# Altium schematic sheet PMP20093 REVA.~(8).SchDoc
size 431 x 279 mm; Date: Not shown in title block; ApprovedBy: Not shown in title block; CheckedBy: Not shown in title block; Author: Not shown in title block; CompanyName: Not shown in title block; Engineer: Not shown in title block; Organization: Not shown in title block; Address1: Not shown in title block; Address2: Not shown in title block; Address3: Not shown in title block; Address4: Not shown in title block; DocumentNumber: 1; Revision: Use project parameter SCH_Rev; SheetNumber: 2; SheetTotal: 3; PageSetup: Record=PageOptions¦CenterHorizontal=True¦CenterVertical=True¦PrintScale=1.00¦XCorrection=1.00¦YCorrection=1.00¦PrintKind=0¦BorderSize=5000000¦LeftOffset=0¦BottomOffset=0¦Orientation=2¦PaperLength=1000¦PaperWidth=1000¦Scale=100¦PaperSource=15¦PrintQuality=600¦MediaType=1¦DitherType=10¦PaperKind=Letter¦PrintScaleMode=1
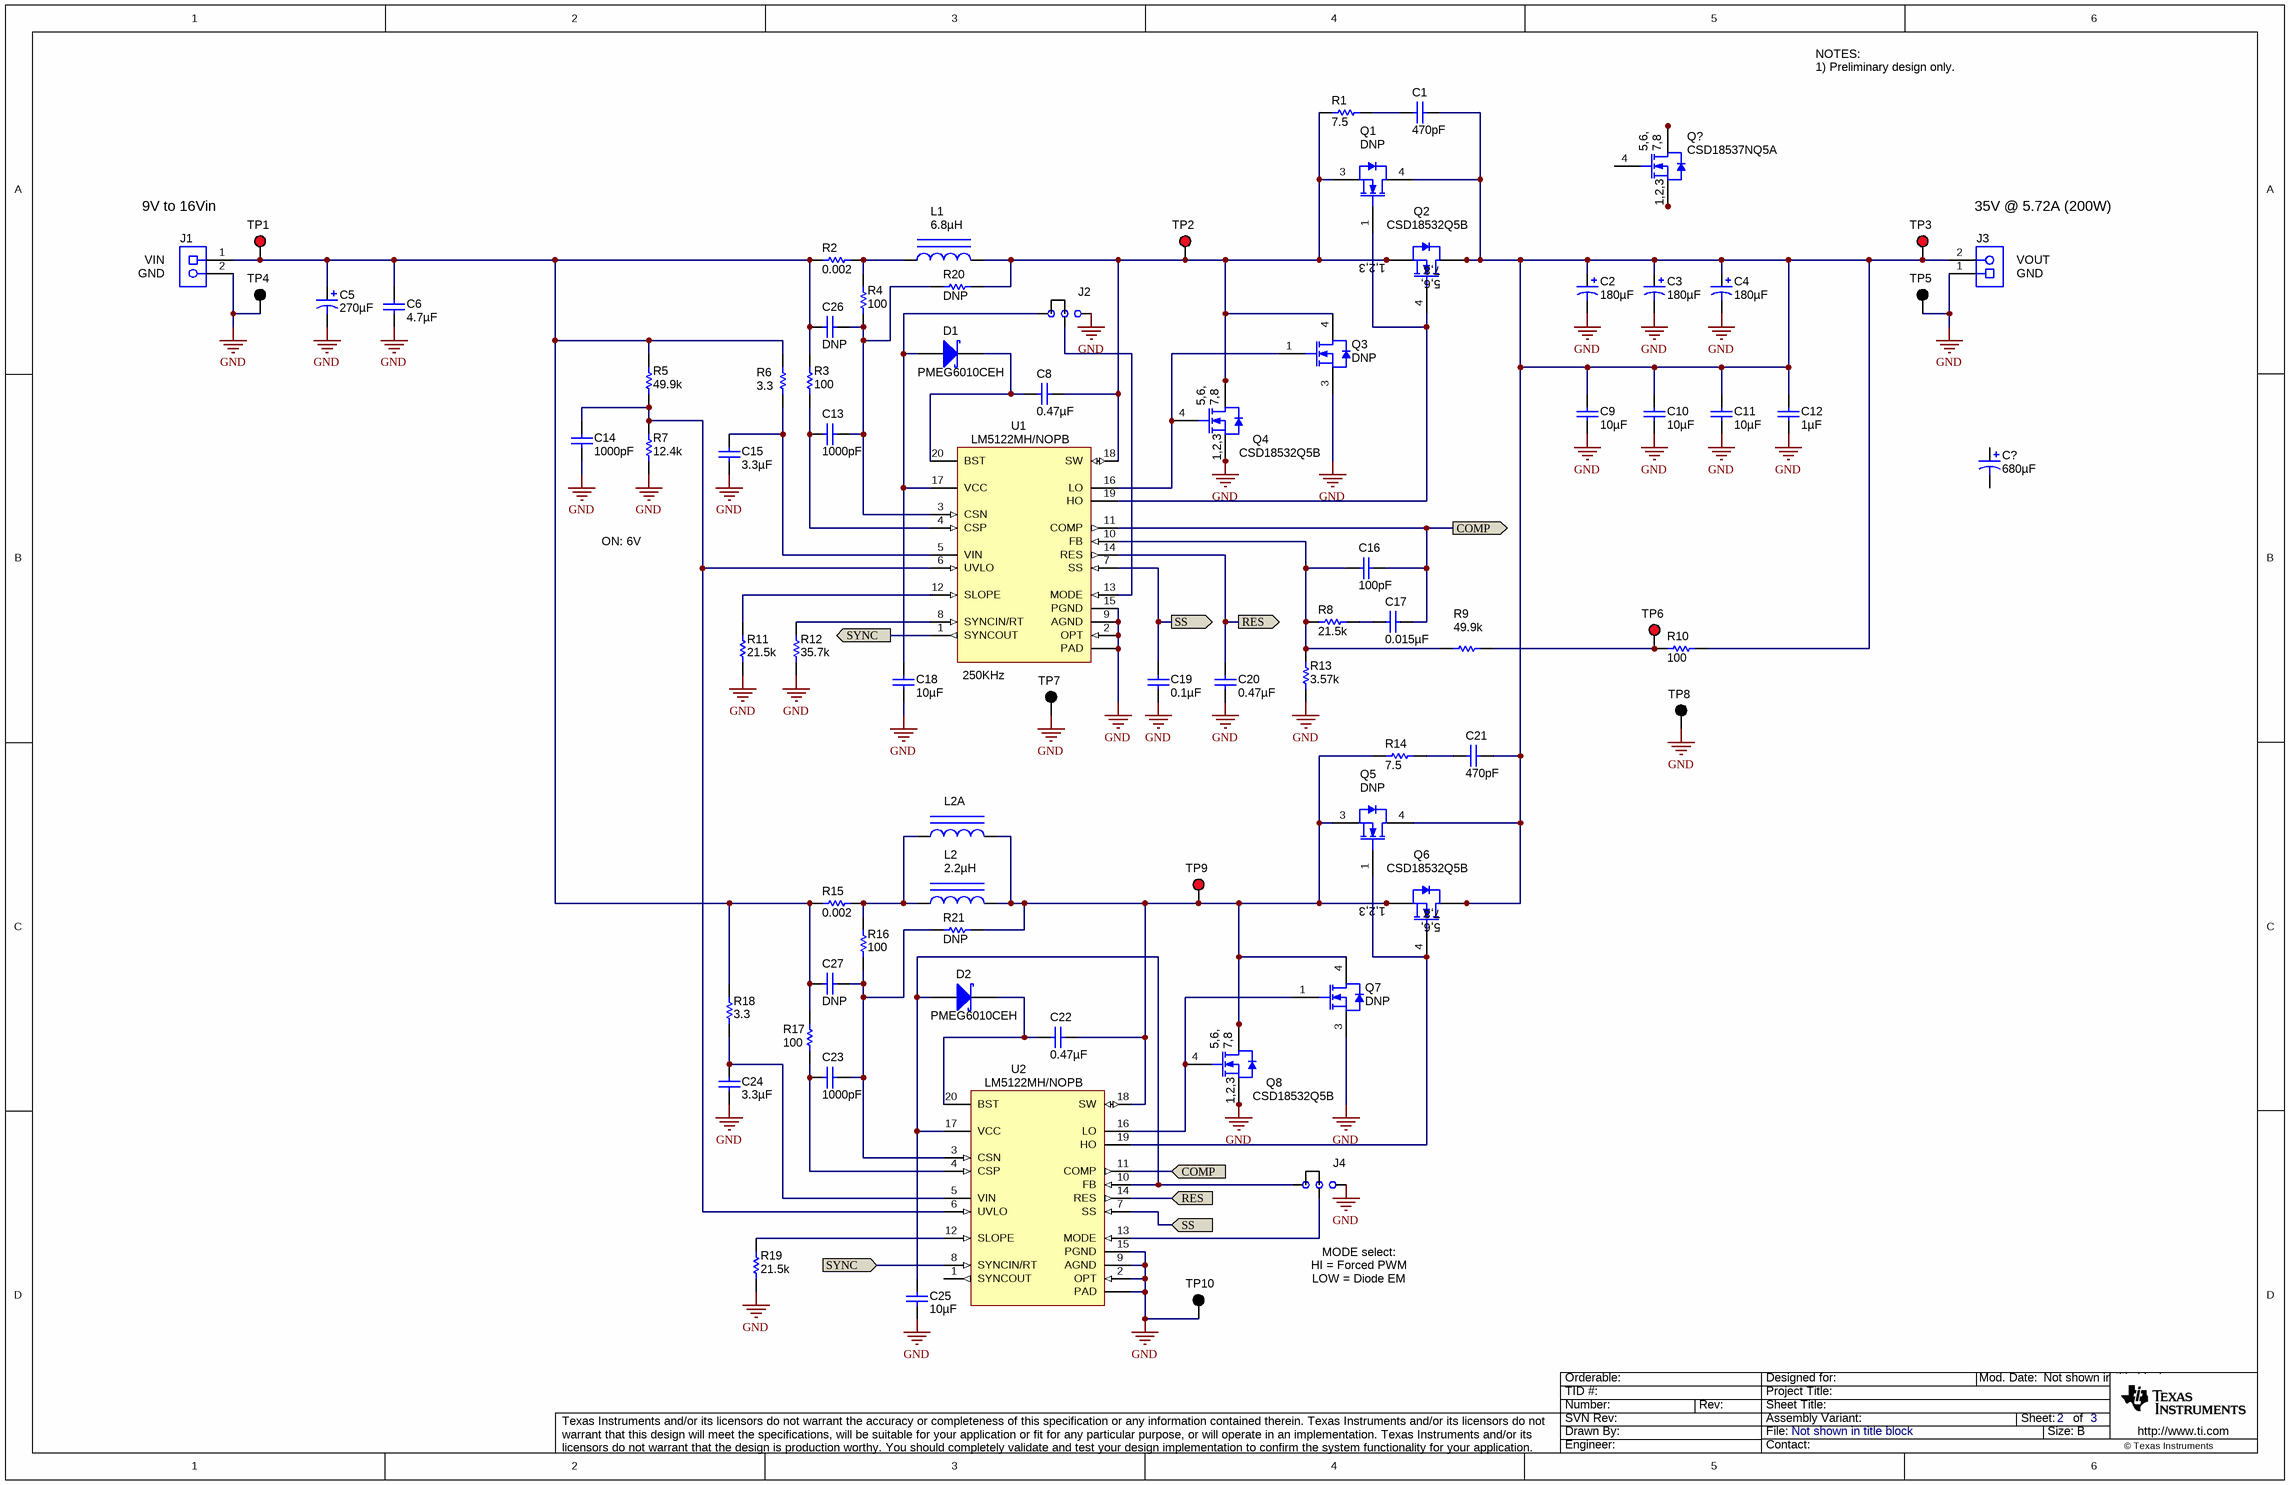
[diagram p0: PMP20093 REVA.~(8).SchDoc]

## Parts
C1  ValueDisplayed: 470pF  [0603]  (hidden comment: C1608C0G1H471J)
C2  ValueDisplayed: 180µF  [SM_RADIAL_8MM]  (hidden comment: 25SVPF180M)
C3  ValueDisplayed: 180µF  [SM_RADIAL_8MM]  (hidden comment: 25SVPF180M)
C4  ValueDisplayed: 180µF  [SM_RADIAL_8MM]  (hidden comment: 25SVPF180M)
C5  ValueDisplayed: 270µF  [SM_RADIAL_10BMM]  (hidden comment: EEHZA1V271P)
C6  ValueDisplayed: 4.7µF  [1210]  (hidden comment: GRM32ER71H475KA88L)
C8  ValueDisplayed: 0.47µF  [0603]  (hidden comment: GRM188R71E474KA12D)
C9  ValueDisplayed: 10µF  [1210]  (hidden comment: C3225X7R1E106M)
C10  ValueDisplayed: 10µF  [1210]  (hidden comment: C3225X7R1E106M)
C11  ValueDisplayed: 10µF  [1210]  (hidden comment: C3225X7R1E106M)
C12  ValueDisplayed: 1µF  [0805_HV]  (hidden comment: C2012X7R1E105K)
C13  ValueDisplayed: 1000pF  [0603]  (hidden comment: GRM188R71H102KA01D)
C14  ValueDisplayed: 1000pF  [0603]  (hidden comment: GRM188R71H102KA01D)
C15  ValueDisplayed: 3.3µF  [1206]  (hidden comment: C3216X7R1H335K160AC)
C16  ValueDisplayed: 100pF  [0603]  (hidden comment: C1608C0G1H101J)
C17  ValueDisplayed: 0.015µF  [0603]  (hidden comment: C1608X7R1H153K)
C18  ValueDisplayed: 10µF  [1206]  (hidden comment: C3216X7R1E106K)
C19  ValueDisplayed: 0.1µF  [0603]  (hidden comment: C1608X7R1H104K)
C20  ValueDisplayed: 0.47µF  [0603]  (hidden comment: GRM188R71E474KA12D)
C21  ValueDisplayed: 470pF  [0603]  (hidden comment: C1608C0G1H471J)
C22  ValueDisplayed: 0.47µF  [0603]  (hidden comment: GRM188R71E474KA12D)
C23  ValueDisplayed: 1000pF  [0603]  (hidden comment: GRM188R71H102KA01D)
C24  ValueDisplayed: 3.3µF  [1206]  (hidden comment: C3216X7R1H335K160AC)
C25  ValueDisplayed: 10µF  [1206]  (hidden comment: C3216X7R1E106K)
C26  ValueDisplayed: DNP  [0603]
C27  ValueDisplayed: DNP  [0603]
C?  ValueDisplayed: 680µF  [ZL_1250x2500]  (hidden comment: 50ZL680MEFC12.5X25)
D1  PMEG6010CEH  [SOD-123F]
D2  PMEG6010CEH  [SOD-123F]
J1  ED120/2DS  [CONN_ED120-2DS]  (value not drawn)
J2  JUMPER_3X100MIL  [HDR100_1X3]  (value not drawn)
J3  ED120/2DS  [CONN_ED120-2DS]  (value not drawn)
J4  JUMPER_3X100MIL  [HDR100_1X3]  (value not drawn)
L1  ValueDisplayed: 6.8µH  [IHLP8787MZ]  (hidden comment: IHLP8787MZER6R8M5A)
L2  ValueDisplayed: 2.2µH  [XAL1010]  (hidden comment: XAL1010-222MEB)
L2A  SER2009-202MLB  [SER2009]  (value not drawn)
Q1  value DNP  [DPAK]
Q2  CSD18532Q5B  [TRANS_NexFET_Q5B]
Q3  value DNP  [DPAK]
Q4  CSD18532Q5B  [TRANS_NexFET_Q5B]
Q5  value DNP  [DPAK]
Q6  CSD18532Q5B  [TRANS_NexFET_Q5B]
Q7  value DNP  [DPAK]
Q8  CSD18532Q5B  [TRANS_NexFET_Q5B]
Q?  CSD18537NQ5A  [TRANS_NexFET_Q5A]
R1  value 7.5  [2010M]  (hidden comment: CRM2010-JW-7R5ELF)
R2  value 0.002  [2512]  (hidden comment: CSNL2512FT2L00)
R3  value 100  [0603_HV]  (hidden comment: ERJ-3GEY0R00V)
R4  value 100  [0603_HV]  (hidden comment: ERJ-3GEY0R00V)
R5  value 49.9k  [0603]  (hidden comment: CRCW060349K9FKEA)
R6  value 3.3  [0603_HV]  (hidden comment: CRCW06033R30JNEA)
R7  value 12.4k  [0603]  (hidden comment: CRCW060312K4FKEA)
R8  value 21.5k  [0603]  (hidden comment: CRCW060321K5FKEA)
R9  value 49.9k  [0603]  (hidden comment: CRCW060349K9FKEA)
R10  value 100  [0603]  (hidden comment: CRCW0603100RFKEA)
R11  value 21.5k  [0603]  (hidden comment: CRCW060321K5FKEA)
R12  ValueDisplayed: 35.7k  [0603]  (hidden comment: CRCW060335K7FKEA)
R13  value 3.57k  [0603]  (hidden comment: CRCW06033K57FKEA)
R14  value 7.5  [2010M]  (hidden comment: CRM2010-JW-7R5ELF)
R15  value 0.002  [2512]  (hidden comment: CSNL2512FT2L00)
R16  value 100  [0603_HV]  (hidden comment: ERJ-3GEY0R00V)
R17  value 100  [0603_HV]  (hidden comment: ERJ-3GEY0R00V)
R18  value 3.3  [0603_HV]  (hidden comment: CRCW06033R30JNEA)
R19  value 21.5k  [0603]  (hidden comment: CRCW060321K5FKEA)
R20  value DNP  [0603]
R21  value DNP  [0603]
TP1  5010  [Keystone5010]  (value not drawn)
TP2  5010  [Keystone5010]  (value not drawn)
TP3  5010  [Keystone5010]  (value not drawn)
TP4  5011  [Keystone5011]  (value not drawn)
TP5  5011  [Keystone5011]  (value not drawn)
TP6  5010  [Keystone5010]  (value not drawn)
TP7  5011  [Keystone5011]  (value not drawn)
TP8  5011  [Keystone5011]  (value not drawn)
TP9  5010  [Keystone5010]  (value not drawn)
TP10  5011  [Keystone5011]  (value not drawn)
U1  LM5122MH/NOPB  [PWP0020A_N]
U2  LM5122MH/NOPB  [PWP0020A_N]

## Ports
COMP, RES, SS, SYNC

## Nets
GND: C2.2(-) C3.2(-) C4.2(-) C5.2(-) C6.2 C9.2 C10.2 C11.2 C12.2 C14.2 C15.2 C18.2 C19.2 C20.1 C24.2 C25.2 J1.2 J2.1 J3.1 J4.1 Q3.3(S) Q4.1(S) Q4.2(S) Q4.3(S) Q7.3(S) Q8.1(S) Q8.2(S) Q8.3(S) R7.1 R11.1 R12.1 R13.1 R19.1 TP4.1 TP5.1 TP7.1 TP8.1 TP10.1 U1.2(OPT) U1.9(AGND) U1.15(PGND) U1.21(PAD) U2.2(OPT) U2.9(AGND) U2.15(PGND) U2.21(PAD)
COMP: C16.2 C17.2 U1.11(COMP) U2.11(COMP) ; port COMP
RES: C20.2 U1.14(RES) U2.14(RES) ; port RES
SS: C19.1 U1.7(SS) U2.7(SS) ; port SS
SYNC: U1.1(SYNCOUT) U2.8(SYNCIN/RT) ; port SYNC
NetC1_1: C1.1 C2.1(+) C3.1(+) C4.1(+) C9.1 C10.1 C11.1 C12.1 C21.1 J3.2 Q1.4(D) Q2.5(D) Q2.6(D) Q2.7(D) Q2.8(D) Q5.4(D) Q6.5(D) Q6.6(D) Q6.7(D) Q6.8(D) R10.2 TP3.1
NetC1_2: C1.2 R1.2
NetC5_1: C5.1(+) C6.1 C26.2 C27.2 J1.1 R2.1 R3.2 R5.2 R6.1 R15.1 R17.2 R18.1 TP1.1
NetC8_1: C8.1 D1.1(K) U1.20(BST)
NetC8_2: C8.2 L1.2 Q1.3(S) Q2.1(S) Q2.2(S) Q2.3(S) Q3.4(D) Q4.5(D) Q4.6(D) Q4.7(D) Q4.8(D) R1.1 R20.2 TP2.1 U1.18(SW)
NetC13_1: C13.1 C26.1 R4.1 R20.1 U1.3(CSN)
NetC13_2: C13.2 R3.1 U1.4(CSP)
NetC14_1: C14.1 R5.1 R7.2 U1.6(UVLO) U2.6(UVLO)
NetC15_1: C15.1 R6.2 U1.5(VIN)
NetC16_1: C16.1 R8.1 R9.1 R13.2 U1.10(FB)
NetC17_1: C17.1 R8.2
NetC18_1: C18.1 D1.2(A) J2.3 U1.17(VCC)
NetC21_2: C21.2 R14.2
NetC22_1: C22.1 D2.1(K) U2.20(BST)
NetC22_2: C22.2 L2.2 L2A.1 Q5.3(S) Q6.1(S) Q6.2(S) Q6.3(S) Q7.4(D) Q8.5(D) Q8.6(D) Q8.7(D) Q8.8(D) R14.1 R21.2 TP9.1 U2.18(SW)
NetC23_1: C23.1 C27.1 R16.1 R21.1 U2.3(CSN)
NetC23_2: C23.2 R17.1 U2.4(CSP)
NetC24_1: C24.1 R18.2 U2.5(VIN)
NetC25_1: C25.1 D2.2(A) J4.3 U2.10(FB) U2.17(VCC)
NetJ2_2: J2.2 U1.13(MODE)
NetJ4_2: J4.2 U2.13(MODE)
NetL1_1: L1.1 R2.2 R4.2
NetL2_1: L2.1 L2A.2 R15.2 R16.2
NetQ1_1: Q1.1(G) Q2.4(G) U1.19(HO)
NetQ3_1: Q3.1(G) Q4.4(G) U1.16(LO)
NetQ5_1: Q5.1(G) Q6.4(G) U2.19(HO)
NetQ7_1: Q7.1(G) Q8.4(G) U2.16(LO)
NetQ?_1: Q?.1(S) Q?.2(S) Q?.3(S)
NetQ?_5: Q?.5(D) Q?.6(D) Q?.7(D) Q?.8(D) Q?.9(D)
NetR9_2: R9.2 R10.1 TP6.1
NetR11_2: R11.2 U1.12(SLOPE)
NetR12_2: R12.2 U1.8(SYNCIN/RT)
NetR19_2: R19.2 U2.12(SLOPE)

Not connected (* = marked no-connect by the designer): C? 1(+) 2(-); Q? 4(G); U2 1(SYNCOUT)

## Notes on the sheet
- NOTES:
  1) Preliminary design only.
- 9V to 16Vin
- 35V @ 5.72A (200W)
- (near J1) VIN
- (near J1) GND
- (near J3) VOUT
- (near J3) GND
- ON: 6V
- (near U1) 250KHz
- MODE select:
- HI = Forced PWM
- LOW = Diode EM

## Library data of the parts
C1 C21 = C1608C0G1H471J: CAP, CERM, 470pF, 50V, +/-5%, C0G/NP0, 0603; Manufacturer: TDK; Polarized: N; CompType: Capacitor; U/M: EA; Cap_F: 0.00000000047; Tolerance_%: 5; ESR_Ohm: 0.0922; Value1: 0.0922 ohm; VDC_V: 50; TaMin_C: -55; TaMax_C: 125
C2-C4 = 4SVP560M: CAP, OS-CON, 180uF, 25V, 4.65Arms, 0.016 ohm, E12; Manufacturer: Sanyo; Polarized: Y; CompType: Capacitor; U/M: EA; Cap_F: 0.00056; Tolerance_%: 20; VDC_V: 25; ESR_Ohm: 0.013; IRMS_A: 4.52; TaMin_C: -55; TaMax_C: 105; Cap_Case: 8.3x8.3x11.9
C5 = EEHZA1V271P: CAP, Polymer Hybrid, 270 µF, 35 V, +/- 20%, 20 ohm, 10x10 SMD; Manufacturer: Panasonic; Polarized: Y; CompType: Capacitor; Value: 270uF; U/M: EA; Cap_F: 0.00027; Tolerance_%: 20; Value1: 20 ohm; VDC_V: 35; Value2: 35V; IRMS_A: 2.5; TaMin_C: -55; TaMax_C: 105; AEC Category: Q200
C6 = GRM32ER71H475KA88L: CAP, CERM, 4.7uF, 50V, +/-10%, X7R, 1210; Manufacturer: MuRata; Polarized: N; CompType: Capacitor; U/M: EA; Cap_F: 0.0000047; Tolerance_%: 10; ESR_Ohm: 0.002; Value1: 0.002 ohm; VDC_V: 50; TaMin_C: -55; TaMax_C: 125
C8 C20 C22 = GRM188R71E474KA12D: CAP, CERM, 0.47uF, 25V, +/-10%, X7R, 0603; Manufacturer: MuRata; Polarized: N; CompType: Capacitor; U/M: EA; Cap_F: 0.00000047; Tolerance_%: 10; Value1: Unknown; VDC_V: 25; TaMin_C: -55; TaMax_C: 125
C9-C11 = C3225X7R1E106M: CAP, CERM, 10uF, 25V, +/-20%, X7R, 1210; Manufacturer: TDK; Polarized: N; CompType: Capacitor; U/M: EA; Cap_F: 0.00001; Tolerance_%: 20; ESR_Ohm: 0.0027; Value1: 0.0027 ohm; VDC_V: 25; IRMS_A: 3; TaMin_C: -55; TaMax_C: 125
C12 = C2012X7R1E105K: CAP, CERM, 1uF, 25V, +/-10%, X7R, 0805; Manufacturer: TDK; Polarized: N; CompType: Capacitor; U/M: EA; Cap_F: 0.000001; Tolerance_%: 10; ESR_Ohm: 0.0075; Value1: 0.0075 ohm; VDC_V: 25; TaMin_C: -55; TaMax_C: 125; Cap_Case: 0805
C13 C14 C23 = GRM188R71H102KA01D: CAP, CERM, 1000pF, 50V, +/-10%, X7R, 0603; Manufacturer: MuRata; Polarized: N; CompType: Capacitor; U/M: EA; Cap_F: 0.000000001; Tolerance_%: 10; Value1: Unknown; VDC_V: 50; TaMin_C: -55; TaMax_C: 125
C15 C24 = C3216X7r1H335K160AC: CAP, CERM, 3.3uF, 50V, +/-10%, X7R, 1206; Manufacturer: TDK; Polarized: N; CompType: Capacitor; U/M: EA; Cap_F: 0.0000033; Tolerance_%: 10; Value1: Unknown; VDC_V: 50; TaMin_C: -55; TaMax_C: 125
C16 = C1608C0G1H101J: CAP, CERM, 100pF, 50V, +/-5%, C0G/NP0, 0603; Manufacturer: TDK; Polarized: N; CompType: Capacitor; U/M: EA; Cap_F: 0.0000000001; Tolerance_%: 5; ESR_Ohm: 0.1679; Value1: 0.1679 ohm; VDC_V: 50; TaMin_C: -55; TaMax_C: 125
C17 = C1608X7R1H103K: CAP, CERM, 0.015uF, 50V, +/-10%, X7R, 0603; Manufacturer: TDK; Polarized: N; CompType: Capacitor; U/M: EA; Cap_F: 0.00000001; Tolerance_%: 10; ESR_Ohm: 0.0539; Value1: 0.0539 ohm; VDC_V: 50; TaMin_C: -55; TaMax_C: 125
C18 C25 = C3216X7R1C475K: CAP, CERM, 10uF, 25V, +/-10%, X7R, 1206; Manufacturer: TDK; Polarized: N; CompType: Capacitor; U/M: EA; Cap_F: 0.0000047; Tolerance_%: 10; ESR_Ohm: 0.0036; Value1: 0.0036 ohm; VDC_V: 25; IRMS_A: 2; TaMin_C: -55; TaMax_C: 125
C19 = C1608X7R1H104K: CAP, CERM, 0.1uF, 50V, +/-10%, X7R, 0603; Manufacturer: TDK; Polarized: N; CompType: Capacitor; U/M: EA; Cap_F: 0.0000001; Tolerance_%: 10; ESR_Ohm: 0.017; Value1: 0.017 ohm; VDC_V: 50; TaMin_C: -55; TaMax_C: 125
C26 C27 = GRM188R71H102KA01D: CAP, DNP; Polarized: N; CompType: Capacitor; U/M: EA; Cap_F: 0.000000001; Value1: Unknown; TempCo: X7R; TaMin_C: -55; TaMax_C: 125
C? = 50ZL560MEFC12.5X25: CAP, AL, 680 µF, 50 V, +/- 20%, 2.86A, 0.021 ohm, TH; Manufacturer: Rubycon; Polarized: Y; CompType: Capacitor; Value: 680uF; U/M: EA; Cap_F: 0.00056; Tolerance_%: 20; VDC_V: 50; Value2: 50V; ESR_ohm: 0.023; IRMS_A: 2.41; TaMin_C: -40; TaMax_C: 105; Cap_Case: 12.5x25mm; AEC Category: Q200; AEC Qualified: N
D1 D2 = PMEG6010CEH,115: Diode, Schottky, 60V, 1A, SOD-123F; Manufacturer: NXP Semiconductor; U/M: EA; Vf_V: 0.57; Value2: 0.57V; Io_A: 1; Vr_V: 60; TJmax_C: 150
J1 J3 = ED120/2DS: TERMINAL BLOCK, 15A, VERT 2POS, TH; Manufacturer: On-Shore Technology; SymbolCreator: a0412235; U/M: EA
J2 J4 = JUMPER_3X100MIL: Header, Male 3-pin, 100mil spacing,; Manufacturer: Sullins; PartNumber: PEC03SAAN; area: 30000; Value: PEC03SAAN
L1 = IHLP8787MZER100M5A: Inductor, Shielded, 6.8 µH, 36A, 0.00284 ohm, AEC-Q200 Grade 0, SMD; Manufacturer: Vishay-Dale; Value: 6.8uH; AEC Category: Q200; AEC Qualified: Y; AEC Grade: 0
L2 = XAL1010-222MEB: Inductor, Shielded, Composite, 2.2uH, 32A, 0.00255 ohm, SMD; Manufacturer: Coilcraft; Ind_H: 2.2E-6; Imax_A: 32; Irms: 32A @ 40C rise; Isat: 34A @ 30% inductance drop; U/M: EA
L2A = SER2009-202MLB: Inductor, Shielded E Core, Ferrite, 2uH, 16A, 0.00063 ohm, SMD; Manufacturer: Coilcraft; Ind_H: 2.0E-6; ValueDisplayed: 2µH; Imax_A: 16; Irms: 54A @ 40C rise; Isat: 16A @ 10% inductance drop; U/M: EA
Q1 Q3 Q5 Q7 = SUD23N06-31L-E3: MOSFET, DPAK, DNP; Manufacturer: Vishay-Siliconix; Alternate Manufacturer: None; U/M: EA; ChType: N; Rdson45_Ohm: 0.045; QgTyp_nC: 11; IdsMax_A: 23
Q2 Q4 Q6 Q8 = CSD18532Q5B: MOSFET, N-CH, 60V, 172A, SON 5x6mm; Manufacturer: Texas Instruments; Alternate Manufacturer: None; U/M: EA; ChType: N; VdsMax_V: 60; Value1: 3.3 ohm; Rdson45_Ohm: 3.3; Value2: 27 nC; QgTyp_nC: 27; Vgs_V: 1.6; IdsMax_A: 172
Q? = CSD18537NQ5A: MOSFET, N-CH, 60 V, 50 A, SON 5x6mm; Manufacturer: Texas Instruments; Alternate Manufacturer: None; U/M: EA; ChType: N; Value: 60V; VdsMax_V: 60; Value1: 0.036 ohm; Rdson45_ohm: 0.036; Value2: 14 nC; QgTyp_nC: 14; Vgs_V: 20; IdsMax_A: 50; AEC Category: Q101
R1 R14 = CRM2010-JW-7R5ELF: RES, 7.5 ohm, 5%, 1W, 2010; Manufacturer: Bourns; CompType: Resistor; Value_Code: 7R50; Tolerance_%: 5; Power_W: 1; VDC_V: 3; TempCo: 100 ppm/C; EIA_Code: E24; U/M: EA
R2 R15 = CSNL2512FT2L00: RES, 0.002 ohm, 1%, 2W, 2512; Manufacturer: Stackpole Electronics Inc; CompType: Resistor; Value_Code: R002; Tolerance_%: 1; Power_W: 2; VDC_V: 200; TempCo: 50 ppm/C; U/M: EA
R3 R4 R16 R17 = ERJ-3GEY0R00V: RES, 0 ohm, 5%, 0.1W, 0603; Manufacturer: Panasonic; CompType: Resistor; Res_ohm: 0; Value_Code: 0000; Tolerance_%: 5; Power_W: 0.1; VDC_V: 50; TempCo: 600 ppm/C; EIA_Code: E24; U/M: EA
R5 R9 = CRCW060349K9FKEA: RES, 49.9k ohm, 1%, 0.1W, 0603; Manufacturer: Vishay-Dale; CompType: Resistor; Res_ohm: 49900; Value_Code: 49k9; Tolerance_%: 1; Power_W: 0.1; VDC_V: 75; TempCo: 100 ppm/C; EIA_Code: E96; U/M: EA
R6 R18 = CRCW06033R30JNEA: RES, 3.3 ohm, 5%, 0.1W, 0603; Manufacturer: Vishay-Dale; CompType: Resistor; Value_Code: 3R30; Tolerance_%: 5; Power_W: 0.1; VDC_V: 75; TempCo: 200 ppm/C; EIA_Code: E24; U/M: EA
R7 = CRCW060312K4FKEA: RES, 12.4k ohm, 1%, 0.1W, 0603; Manufacturer: Vishay-Dale; CompType: Resistor; Res_ohm: 12400; Value_Code: 12k4; Tolerance_%: 1; Power_W: 0.1; VDC_V: 75; TempCo: 100 ppm/C; EIA_Code: E96; U/M: EA
R8 R11 R19 = CRCW060321K5FKEA: RES, 21.5k ohm, 1%, 0.1W, 0603; Manufacturer: Vishay-Dale; CompType: Resistor; Res_ohm: 21500; Value_Code: 21k5; Tolerance_%: 1; Power_W: 0.1; VDC_V: 75; TempCo: 100 ppm/C; EIA_Code: E96; U/M: EA
R10 = CRCW0603100RFKEA: RES, 100 ohm, 1%, 0.1W, 0603; Manufacturer: Vishay-Dale; CompType: Resistor; Value_Code: 100R; Tolerance_%: 1; Power_W: 0.1; VDC_V: 75; TempCo: 100 ppm/C; EIA_Code: E96; U/M: EA
R12 = CRCW060335K7FKEA: RES, 35.7 k, 1%, 0.1 W, 0603; Manufacturer: Vishay-Dale; CompType: Resistor; Value: 35.7k; Res_ohm: 35700; Value_Code: 35k7; Tolerance_%: 1; Power_W: 0.1; Value2: 0.1W; VDC_V: 75; TempCo: 100 ppm/C; EIA_Code: E96; U/M: EA; AEC Category: Q200
R13 = CRCW06033K57FKEA: RES, 3.57k ohm, 1%, 0.1W, 0603; Manufacturer: Vishay-Dale; CompType: Resistor; Res_ohm: 3570; Value_Code: 3k57; Tolerance_%: 1; Power_W: 0.1; VDC_V: 75; TempCo: 100 ppm/C; EIA_Code: E96; U/M: EA
R20 R21 = CRCW060315K0FKEA: RES, DNP; Manufacturer: Vishay-Dale; CompType: Resistor; Res_ohm: 15000; Value_Code: 15k0; Tolerance_%: 1; Value1: 1%; Power_W: 0.1; TempCo: 100 ppm/C; EIA_Code: E96; U/M: EA
TP1-TP3 TP6 TP9 = 5010: Test Point, Multipurpose, Red, TH; Manufacturer: Keystone; CompType: Test Point Loop; U/M: EA
TP4 TP5 TP7 TP8 TP10 = 5011: Test Point, Multipurpose, Black, TH; Manufacturer: Keystone; CompType: Test Point Loop; U/M: EA
U1 U2 = LM5122MH/NOPB: Wide Input Synchronous Boost Controller with Multiple Phase Capability, PWP0020A; Alternate Manufacturer: None; Manufacturer: Texas Instruments; SymbolCreator: a0411947; CompType: IC; U/M: EA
